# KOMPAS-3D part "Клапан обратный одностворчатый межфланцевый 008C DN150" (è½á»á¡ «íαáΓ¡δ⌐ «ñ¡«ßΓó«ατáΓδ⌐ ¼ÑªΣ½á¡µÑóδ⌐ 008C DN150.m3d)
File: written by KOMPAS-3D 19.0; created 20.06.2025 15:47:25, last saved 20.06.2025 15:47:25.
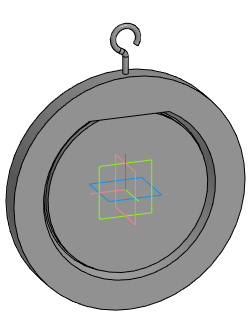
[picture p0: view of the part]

Document properties: Полное имя файла: E:\Dendor Работа Сачек\3D для проектировщиков\5.1 Тип 008C. Клапан обратный одностворчатый межфланцевый\stp_Клапан обратный одностворчатый межфланцевый 008C\Клапан обратный одностворчатый межфланцевый 008C DN150.m3d

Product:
- Part/product: Клапан обратный одностворчатый межфланцевый 008C DN150

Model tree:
1. Операция без истории:1  (labels: Клапан обратный одностворчатый межфланцевый 008C DN150)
